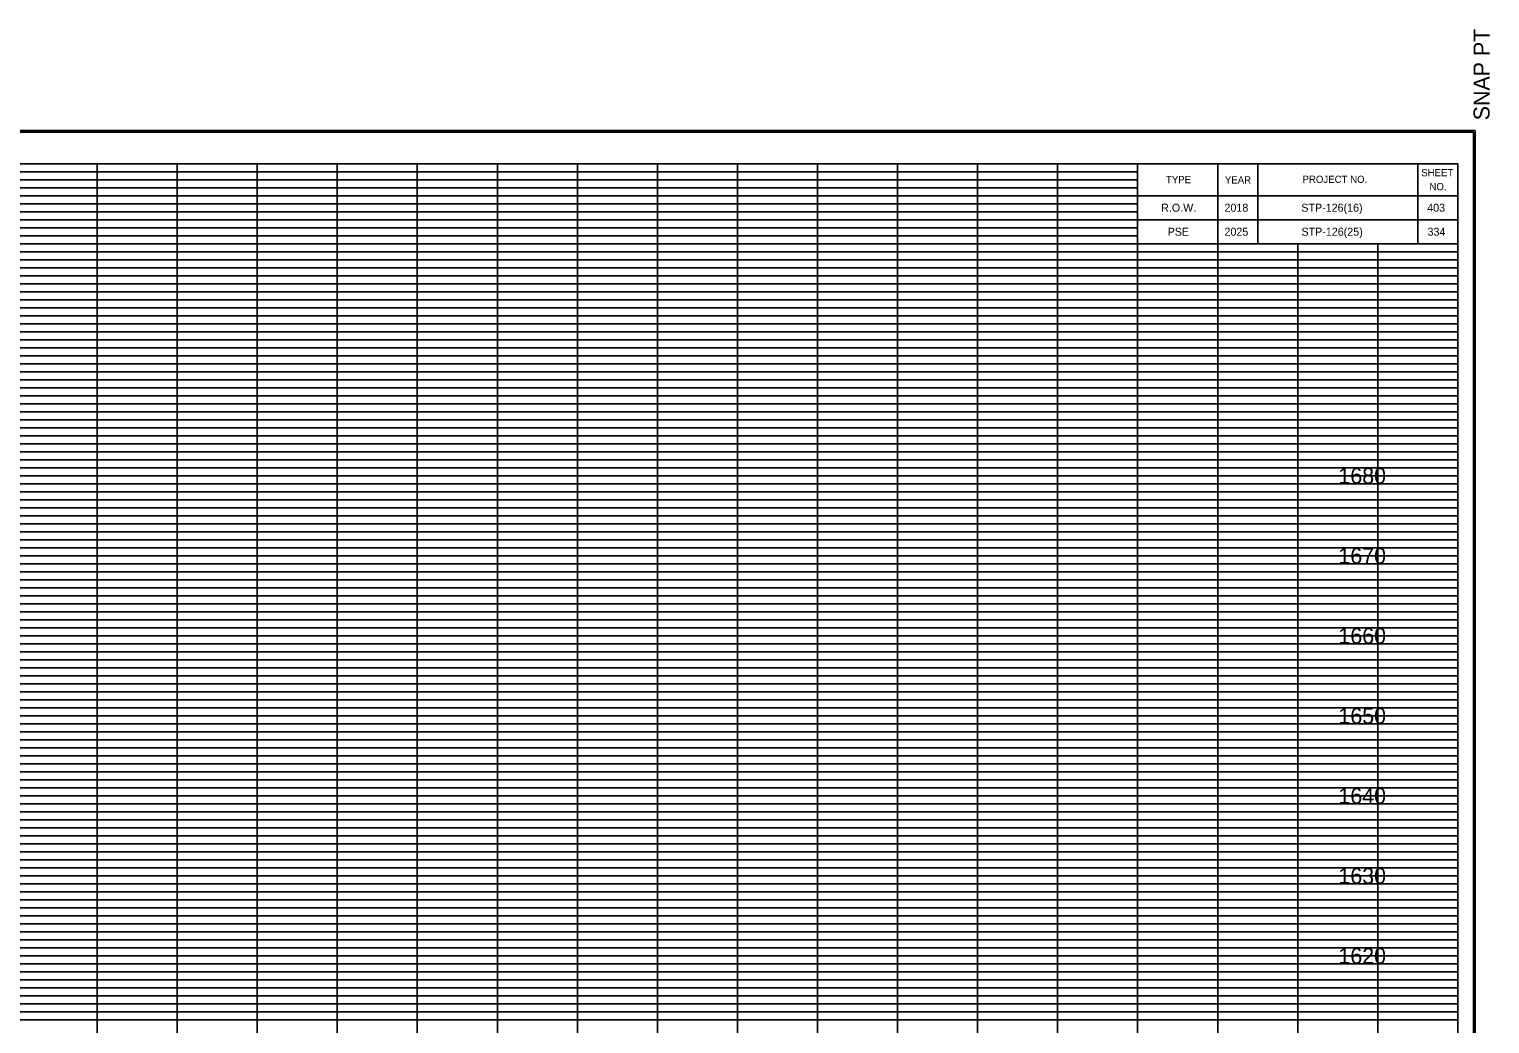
# Model space of a CAD drawing. Extents: x 980 to 1380, y 1248 to 3387.
# Drawn here: x 1141.5 to 1324, y 1642.5 to 1766.8 of the extents above; entities that cross this region are included whole.
import ezdxf

# ---------------------------------------------------------------- set-up
doc = ezdxf.new("R2010")
doc.units = 0
for name, color, linetype in [('DESIGN - SCRATCH - User 1', 7, 'Continuous'), ('DESIGN - SHEET - Corner Text', 7, 'Continuous'), ('DESIGN - SHEET - Light Grid', 7, 'Continuous'), ('DESIGN - SHEET - Linework', 7, 'Continuous'), ('DESIGN - SHEET - Plot Shape', 7, 'Continuous'), ('DESIGN - TYPICAL - Text', 7, 'Continuous')]:
    doc.layers.add(name, color=color, linetype=linetype)

# ---------------------------------------------------------------- blocks, each defined once
blk = doc.blocks.new('XSTSHT')
at = {"layer": 'DESIGN - SCRATCH - User 1'}
for p, q in [((28.5, 20.45), (28.5, 20.45)), ((29.24, 20.45), (29.24, 20.45)), ((30.49, 20.45), (30.49, 20.45)), ((31.74, 20.45), (31.74, 20.45)), ((28.5, 20.15), (28.5, 20.15)), ((29.24, 20.15), (29.24, 20.15)), ((30.49, 20.15), (30.49, 20.15)), ((31.74, 20.15), (31.74, 20.15))]:
    blk.add_line(p, q, dxfattribs=at)
at = {"layer": 'DESIGN - SHEET - Light Grid'}
for p, q in [((8, 20.9), (16, 20.9)), ((16, 20.9), (24, 20.9)), ((24, 20.9), (28, 20.9)), ((8, 20.8), (16, 20.8)), ((8, 20.7), (16, 20.7)), ((16, 20.8), (24, 20.8)), ((16, 20.7), (24, 20.7)), ((24, 20.8), (28, 20.8)), ((24, 20.7), (28, 20.7)), ((8, 20.6), (16, 20.6)), ((8, 20.5), (16, 20.5)), ((16, 20.6), (24, 20.6)), ((16, 20.5), (24, 20.5)), ((24, 20.6), (28, 20.6)), ((24, 20.5), (28, 20.5)), ((8, 20.4), (16, 20.4)), ((8, 20.3), (16, 20.3)), ((16, 20.4), (24, 20.4)), ((16, 20.3), (24, 20.3)), ((24, 20.4), (28, 20.4)), ((24, 20.3), (28, 20.3)), ((8, 20.2), (16, 20.2)), ((8, 20.1), (16, 20.1)), ((16, 20.2), (24, 20.2)), ((16, 20.1), (24, 20.1)), ((24, 20.2), (28, 20.2)), ((24, 20.1), (28, 20.1)), ((8, 19.9), (16, 19.9)), ((16, 19.9), (24, 19.9)), ((24, 19.9), (32, 19.9)), ((8, 19.8), (16, 19.8)), ((16, 19.8), (24, 19.8)), ((24, 19.8), (32, 19.8)), ((8, 19.7), (16, 19.7)), ((8, 19.6), (16, 19.6)), ((16, 19.7), (24, 19.7)), ((16, 19.6), (24, 19.6)), ((24, 19.7), (32, 19.7)), ((24, 19.6), (32, 19.6)), ((8, 19.5), (16, 19.5)), ((8, 19.4), (16, 19.4)), ((16, 19.5), (24, 19.5)), ((16, 19.4), (24, 19.4)), ((24, 19.5), (32, 19.5)), ((24, 19.4), (32, 19.4)), ((8, 19.3), (16, 19.3)), ((8, 19.2), (16, 19.2)), ((16, 19.3), (24, 19.3)), ((16, 19.2), (24, 19.2)), ((24, 19.3), (32, 19.3)), ((24, 19.2), (32, 19.2)), ((8, 19.1), (16, 19.1)), ((16, 19.1), (24, 19.1)), ((24, 19.1), (32, 19.1)), ((8, 18.9), (16, 18.9)), ((8, 18.8), (16, 18.8)), ((16, 18.9), (24, 18.9)), ((16, 18.8), (24, 18.8)), ((24, 18.9), (32, 18.9)), ((24, 18.8), (32, 18.8)), ((8, 18.7), (16, 18.7)), ((16, 18.7), (24, 18.7)), ((24, 18.7), (32, 18.7)), ((8, 18.6), (16, 18.6)), ((8, 18.5), (16, 18.5)), ((16, 18.6), (24, 18.6)), ((16, 18.5), (24, 18.5)), ((24, 18.6), (32, 18.6)), ((24, 18.5), (32, 18.5)), ((8, 18.4), (16, 18.4)), ((8, 18.3), (16, 18.3)), ((16, 18.4), (24, 18.4)), ((16, 18.3), (24, 18.3)), ((24, 18.4), (32, 18.4)), ((24, 18.3), (32, 18.3)), ((8, 18.2), (16, 18.2)), ((8, 18.1), (16, 18.1)), ((16, 18.2), (24, 18.2)), ((16, 18.1), (24, 18.1)), ((24, 18.2), (32, 18.2)), ((24, 18.1), (32, 18.1)), ((8, 17.9), (16, 17.9)), ((16, 17.9), (24, 17.9)), ((24, 17.9), (32, 17.9)), ((8, 17.8), (16, 17.8)), ((16, 17.8), (24, 17.8)), ((24, 17.8), (32, 17.8)), ((8, 17.7), (16, 17.7)), ((8, 17.6), (16, 17.6)), ((16, 17.7), (24, 17.7)), ((16, 17.6), (24, 17.6)), ((24, 17.7), (32, 17.7)), ((24, 17.6), (32, 17.6)), ((8, 17.5), (16, 17.5)), ((8, 17.4), (16, 17.4)), ((16, 17.5), (24, 17.5)), ((16, 17.4), (24, 17.4)), ((24, 17.5), (32, 17.5)), ((24, 17.4), (32, 17.4)), ((8, 17.3), (16, 17.3)), ((8, 17.2), (16, 17.2)), ((16, 17.3), (24, 17.3)), ((16, 17.2), (24, 17.2)), ((24, 17.3), (32, 17.3)), ((24, 17.2), (32, 17.2)), ((8, 17.1), (16, 17.1)), ((16, 17.1), (24, 17.1)), ((24, 17.1), (32, 17.1)), ((8, 16.9), (16, 16.9)), ((8, 16.8), (16, 16.8)), ((16, 16.9), (24, 16.9)), ((16, 16.8), (24, 16.8)), ((24, 16.9), (32, 16.9)), ((24, 16.8), (32, 16.8)), ((8, 16.7), (16, 16.7)), ((16, 16.7), (24, 16.7)), ((24, 16.7), (32, 16.7)), ((8, 16.6), (16, 16.6)), ((8, 16.5), (16, 16.5)), ((16, 16.6), (24, 16.6)), ((16, 16.5), (24, 16.5)), ((24, 16.6), (32, 16.6)), ((24, 16.5), (32, 16.5)), ((8, 16.4), (16, 16.4)), ((8, 16.3), (16, 16.3)), ((16, 16.4), (24, 16.4)), ((16, 16.3), (24, 16.3)), ((24, 16.4), (32, 16.4)), ((24, 16.3), (32, 16.3)), ((8, 16.2), (16, 16.2)), ((8, 16.1), (16, 16.1)), ((16, 16.2), (24, 16.2)), ((16, 16.1), (24, 16.1)), ((24, 16.2), (32, 16.2)), ((24, 16.1), (32, 16.1)), ((8, 15.9), (16, 15.9)), ((16, 15.9), (24, 15.9)), ((24, 15.9), (32, 15.9)), ((8, 15.8), (16, 15.8)), ((8, 15.7), (16, 15.7)), ((16, 15.8), (24, 15.8)), ((16, 15.7), (24, 15.7)), ((24, 15.8), (32, 15.8)), ((24, 15.7), (32, 15.7)), ((8, 15.6), (16, 15.6)), ((16, 15.6), (24, 15.6)), ((24, 15.6), (32, 15.6)), ((8, 15.5), (16, 15.5)), ((8, 15.4), (16, 15.4)), ((16, 15.5), (24, 15.5)), ((16, 15.4), (24, 15.4)), ((24, 15.5), (32, 15.5)), ((24, 15.4), (32, 15.4)), ((8, 15.3), (16, 15.3)), ((8, 15.2), (16, 15.2)), ((16, 15.3), (24, 15.3)), ((16, 15.2), (24, 15.2)), ((24, 15.3), (32, 15.3)), ((24, 15.2), (32, 15.2)), ((8, 15.1), (16, 15.1)), ((16, 15.1), (24, 15.1)), ((24, 15.1), (32, 15.1)), ((8, 14.9), (16, 14.9)), ((8, 14.8), (16, 14.8)), ((16, 14.9), (24, 14.9)), ((16, 14.8), (24, 14.8)), ((24, 14.9), (32, 14.9)), ((24, 14.8), (32, 14.8)), ((8, 14.7), (16, 14.7)), ((8, 14.6), (16, 14.6)), ((16, 14.7), (24, 14.7)), ((16, 14.6), (24, 14.6)), ((24, 14.7), (32, 14.7)), ((24, 14.6), (32, 14.6)), ((8, 14.5), (16, 14.5)), ((16, 14.5), (24, 14.5)), ((24, 14.5), (32, 14.5)), ((8, 14.4), (16, 14.4)), ((8, 14.3), (16, 14.3)), ((16, 14.4), (24, 14.4)), ((16, 14.3), (24, 14.3)), ((24, 14.4), (32, 14.4)), ((24, 14.3), (32, 14.3)), ((8, 14.2), (16, 14.2)), ((8, 14.1), (16, 14.1)), ((16, 14.2), (24, 14.2)), ((16, 14.1), (24, 14.1)), ((24, 14.2), (32, 14.2)), ((24, 14.1), (32, 14.1)), ((8, 13.9), (16, 13.9)), ((16, 13.9), (24, 13.9)), ((24, 13.9), (32, 13.9)), ((8, 13.8), (16, 13.8)), ((8, 13.7), (16, 13.7)), ((16, 13.8), (24, 13.8)), ((16, 13.7), (24, 13.7)), ((24, 13.8), (32, 13.8)), ((24, 13.7), (32, 13.7)), ((8, 13.6), (16, 13.6)), ((16, 13.6), (24, 13.6)), ((24, 13.6), (32, 13.6)), ((8, 13.5), (16, 13.5)), ((8, 13.4), (16, 13.4)), ((16, 13.5), (24, 13.5)), ((16, 13.4), (24, 13.4)), ((24, 13.5), (32, 13.5)), ((24, 13.4), (32, 13.4)), ((8, 13.3), (16, 13.3)), ((8, 13.2), (16, 13.2)), ((16, 13.3), (24, 13.3)), ((16, 13.2), (24, 13.2)), ((24, 13.3), (32, 13.3)), ((24, 13.2), (32, 13.2)), ((8, 13.1), (16, 13.1)), ((16, 13.1), (24, 13.1)), ((24, 13.1), (32, 13.1)), ((8, 12.9), (16, 12.9)), ((8, 12.8), (16, 12.8)), ((16, 12.9), (24, 12.9)), ((16, 12.8), (24, 12.8)), ((24, 12.9), (32, 12.9)), ((24, 12.8), (32, 12.8)), ((8, 12.7), (16, 12.7)), ((8, 12.6), (16, 12.6)), ((16, 12.7), (24, 12.7)), ((16, 12.6), (24, 12.6)), ((24, 12.7), (32, 12.7)), ((24, 12.6), (32, 12.6)), ((8, 12.5), (16, 12.5)), ((16, 12.5), (24, 12.5)), ((24, 12.5), (32, 12.5)), ((8, 12.4), (16, 12.4)), ((8, 12.3), (16, 12.3)), ((16, 12.4), (24, 12.4)), ((16, 12.3), (24, 12.3)), ((24, 12.4), (32, 12.4)), ((24, 12.3), (32, 12.3)), ((8, 12.2), (16, 12.2)), ((8, 12.1), (16, 12.1)), ((16, 12.2), (24, 12.2)), ((16, 12.1), (24, 12.1)), ((24, 12.2), (32, 12.2)), ((24, 12.1), (32, 12.1)), ((8, 11.9), (16, 11.9)), ((16, 11.9), (24, 11.9)), ((24, 11.9), (32, 11.9)), ((8, 11.8), (16, 11.8)), ((8, 11.7), (16, 11.7)), ((16, 11.8), (24, 11.8)), ((16, 11.7), (24, 11.7)), ((24, 11.8), (32, 11.8)), ((24, 11.7), (32, 11.7)), ((8, 11.6), (16, 11.6)), ((8, 11.5), (16, 11.5)), ((16, 11.6), (24, 11.6)), ((16, 11.5), (24, 11.5)), ((24, 11.6), (32, 11.6)), ((24, 11.5), (32, 11.5)), ((8, 11.4), (16, 11.4)), ((16, 11.4), (24, 11.4)), ((24, 11.4), (32, 11.4)), ((8, 11.3), (16, 11.3)), ((8, 11.2), (16, 11.2)), ((16, 11.3), (24, 11.3)), ((16, 11.2), (24, 11.2)), ((24, 11.3), (32, 11.3)), ((24, 11.2), (32, 11.2)), ((8, 11.1), (16, 11.1)), ((16, 11.1), (24, 11.1)), ((24, 11.1), (32, 11.1)), ((8, 10.9), (16, 10.9)), ((8, 10.8), (16, 10.8)), ((16, 10.9), (24, 10.9)), ((16, 10.8), (24, 10.8)), ((24, 10.9), (32, 10.9)), ((24, 10.8), (32, 10.8)), ((8, 10.7), (16, 10.7)), ((8, 10.6), (16, 10.6)), ((16, 10.7), (24, 10.7)), ((16, 10.6), (24, 10.6)), ((24, 10.7), (32, 10.7)), ((24, 10.6), (32, 10.6)), ((8, 10.5), (16, 10.5)), ((16, 10.5), (24, 10.5)), ((24, 10.5), (32, 10.5)), ((8, 10.4), (16, 10.4)), ((8, 10.3), (16, 10.3)), ((16, 10.4), (24, 10.4)), ((16, 10.3), (24, 10.3)), ((24, 10.4), (32, 10.4)), ((24, 10.3), (32, 10.3))]:
    blk.add_line(p, q, dxfattribs=at)
at = {"layer": 'DESIGN - SHEET - Linework'}
for p, q in [((-1.823, 21.414), (32.217, 21.414)), ((32.217, 21.414), (32.217, -0.414)), ((15, 0), (15, 21)), ((16, 0), (16, 21)), ((17, 0), (17, 21)), ((18, 0), (18, 21)), ((19, 0), (19, 21)), ((20, 0), (20, 21)), ((21, 0), (21, 21)), ((22, 0), (22, 21)), ((23, 0), (23, 21)), ((24, 0), (24, 21)), ((25, 0), (25, 21)), ((26, 0), (26, 21)), ((27, 0), (27, 21)), ((0, 20), (28, 20)), ((28, 0), (28, 20)), ((29, 0), (29, 20)), ((30, 0), (30, 20)), ((31, 0), (31, 20)), ((0, 19), (32, 19)), ((0, 18), (32, 18)), ((0, 17), (32, 17)), ((0, 16), (32, 16)), ((0, 15), (32, 15)), ((0, 14), (32, 14)), ((0, 13), (32, 13)), ((0, 12), (32, 12)), ((0, 11), (32, 11))]:
    blk.add_line(p, q, dxfattribs=at)
for points in [[(0, 21), (0, 0), (32, 0), (32, 21), (0, 21)], [(28, 21), (28, 20), (32, 20), (32, 21), (31.5, 21), (31.5, 20), (29.5, 20), (29.5, 21), (29, 21), (29, 20), (32, 20), (28, 20), (28, 20.3), (32, 20.3), (32, 20.6), (28, 20.6)]]:
    blk.add_lwpolyline(points, dxfattribs=at)
at = {"layer": 'DESIGN - SHEET - Plot Shape'}
for points in [[(-1.803, 21.394), (32.197, 21.394), (32.197, -0.394), (-1.803, -0.394)], [(-0.85, 21), (32, 21), (32, -0.25), (-0.85, -0.25)]]:
    blk.add_lwpolyline(points, close=True, dxfattribs=at)
at = {"layer": 'DESIGN - SHEET - Corner Text'}
blk.add_text('  SNAP PT', height=0.2, rotation=90, dxfattribs=at).set_placement((32.397, 21.394))
for s, p in [('TYPE', (28.354, 20.756)), ('YEAR', (29.09, 20.752)), ('PROJECT NO.', (30.06, 20.76)), ('SHEET', (31.543, 20.843)), ('NO.', (31.646, 20.669))]:
    blk.add_text(s, height=0.09, dxfattribs=at).set_placement(p)

msp = doc.modelspace()

# ---------------------------------------------------------------- linework, layer by layer
at = {"layer": 'DESIGN - SHEET - Plot Shape'}
msp.add_lwpolyline([(991.5, 1537.5), (1320, 1537.5), (1320, 1750), (991.5, 1750)], close=True, dxfattribs=at)

# ---------------------------------------------------------------- block references
at = {"layer": 'DESIGN - TYPICAL - Text', "xscale": 10, "yscale": 10}
msp.add_blockref('XSTSHT', (1000, 1540), dxfattribs=at)

# ---------------------------------------------------------------- texts
at = {"layer": 'DESIGN - SHEET - Corner Text'}
for s, p in [('R.O.W.', (1282.94, 1744)), ('2018', (1290.85, 1744)), ('STP-126(16)', (1300.45, 1744)), ('403', (1316.18, 1744)), ('PSE', (1283.75, 1741)), ('2025', (1290.85, 1741)), ('STP-126(25)', (1300.47, 1741)), ('334', (1316.22, 1741))]:
    msp.add_text(s, height=1, dxfattribs=at).set_placement(p)
at = {"layer": 'DESIGN - TYPICAL - Text'}
for s, p in [('     1680     ', (1301.37, 1710)), ('     1670     ', (1301.37, 1700)), ('     1660     ', (1301.37, 1690)), ('     1650     ', (1301.37, 1680)), ('     1640     ', (1301.37, 1670)), ('     1630     ', (1301.37, 1660)), ('     1620     ', (1301.37, 1650))]:
    msp.add_text(s, height=2, dxfattribs=at).set_placement(p)

doc.saveas('drawing.dxf')
